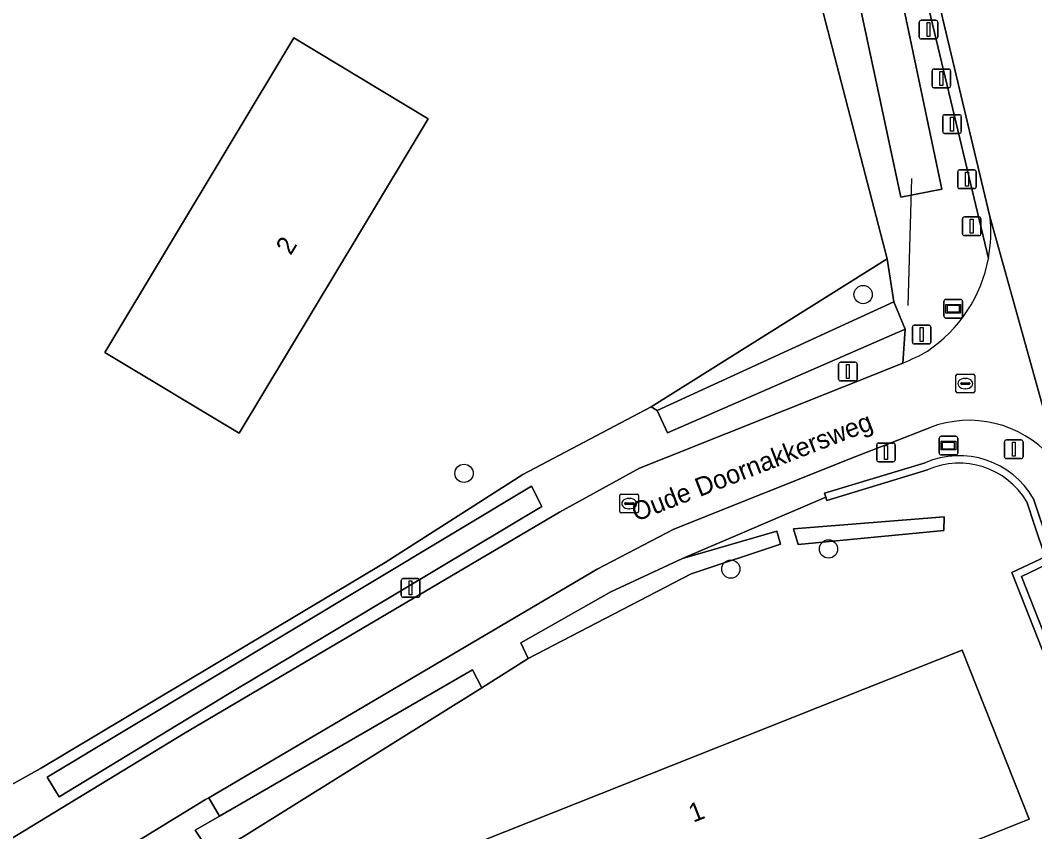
# Model space of a CAD drawing. Extents: x 164494 to 166241, y 382475 to 384495.
# Drawn here: x 164761.6 to 164815.9, y 383480 to 383523.4 of the extents above; entities that cross this region are included whole.
import ezdxf

# ---------------------------------------------------------------- set-up
doc = ezdxf.new("R2010")
doc.units = 0
for name, color, linetype in [('IMGEO_Afsluitpaal', 7, 'Continuous'), ('IMGEO_Berm_halfverhard', 7, 'Continuous'), ('IMGEO_Boom', 7, 'Continuous'), ('IMGEO_Duiker', 7, 'Continuous'), ('IMGEO_Erf', 7, 'Continuous'), ('IMGEO_Groenvoorziening', 7, 'Continuous'), ('IMGEO_Haag', 7, 'Continuous'), ('IMGEO_Lichtmast', 7, 'Continuous'), ('IMGEO_Openbare_ruimte_label', 7, 'Continuous'), ('IMGEO_Pand', 7, 'Continuous'), ('IMGEO_Pand_nummerreeks', 7, 'Continuous'), ('IMGEO_Rijbaan_lokaal_gesloten', 7, 'Continuous'), ('IMGEO_Rijbaan_lokaal_open', 7, 'Continuous'), ('IMGEO_Rioolput', 7, 'Continuous'), ('IMGEO_Straatnaambord', 7, 'Continuous'), ('IMGEO_Verklikker', 7, 'Continuous'), ('IMGEO_Voetpad_open', 7, 'Continuous'), ('IMGEO_Waterloop', 7, 'Continuous')]:
    doc.layers.add(name, color=color, linetype=linetype)

msp = doc.modelspace()

# ---------------------------------------------------------------- linework, layer by layer
at = {"layer": 'IMGEO_Afsluitpaal'}
for p, q in [((164809.71, 383522.472), (164809.71, 383523.272)), ((164809.71, 383523.272), (164809.71, 383522.472)), ((164809.81, 383523.372), (164810.6, 383523.372)), ((164810.6, 383523.372), (164809.81, 383523.372)), ((164810.7, 383523.272), (164810.7, 383522.472)), ((164810.7, 383522.472), (164810.7, 383523.272)), ((164810.6, 383522.372), (164809.81, 383522.372)), ((164809.81, 383522.372), (164810.6, 383522.372)), ((164810.396, 383519.864), (164810.396, 383520.664)), ((164810.396, 383520.664), (164810.396, 383519.864)), ((164810.496, 383520.764), (164811.286, 383520.764)), ((164811.286, 383520.764), (164810.496, 383520.764)), ((164811.386, 383520.664), (164811.386, 383519.864)), ((164811.386, 383519.864), (164811.386, 383520.664)), ((164811.286, 383519.764), (164810.496, 383519.764)), ((164810.496, 383519.764), (164811.286, 383519.764)), ((164810.968, 383517.418), (164810.968, 383518.218)), ((164810.968, 383518.218), (164810.968, 383517.418)), ((164811.068, 383518.318), (164811.858, 383518.318)), ((164811.858, 383518.318), (164811.068, 383518.318)), ((164811.958, 383518.218), (164811.958, 383517.418)), ((164811.958, 383517.418), (164811.958, 383518.218)), ((164811.858, 383517.318), (164811.068, 383517.318)), ((164811.068, 383517.318), (164811.858, 383517.318)), ((164811.766, 383514.464), (164811.766, 383515.264)), ((164811.766, 383515.264), (164811.766, 383514.464)), ((164811.866, 383515.364), (164812.656, 383515.364)), ((164812.656, 383515.364), (164811.866, 383515.364)), ((164812.756, 383515.264), (164812.756, 383514.464)), ((164812.756, 383514.464), (164812.756, 383515.264)), ((164812.656, 383514.364), (164811.866, 383514.364)), ((164811.866, 383514.364), (164812.656, 383514.364)), ((164812.021, 383511.95), (164812.021, 383512.75)), ((164812.021, 383512.75), (164812.021, 383511.95)), ((164812.121, 383512.85), (164812.911, 383512.85)), ((164812.911, 383512.85), (164812.121, 383512.85)), ((164813.011, 383512.75), (164813.011, 383511.95)), ((164813.011, 383511.95), (164813.011, 383512.75)), ((164812.911, 383511.85), (164812.121, 383511.85)), ((164812.121, 383511.85), (164812.911, 383511.85)), ((164809.341, 383506.155), (164809.341, 383506.955)), ((164809.341, 383506.955), (164809.341, 383506.155)), ((164809.441, 383507.055), (164810.231, 383507.055)), ((164810.231, 383507.055), (164809.441, 383507.055)), ((164810.331, 383506.955), (164810.331, 383506.155)), ((164810.331, 383506.155), (164810.331, 383506.955)), ((164810.231, 383506.055), (164809.441, 383506.055)), ((164809.441, 383506.055), (164810.231, 383506.055)), ((164814.269, 383500.022), (164814.269, 383500.822)), ((164814.269, 383500.822), (164814.269, 383500.022)), ((164814.369, 383500.922), (164815.159, 383500.922)), ((164815.159, 383500.922), (164814.369, 383500.922)), ((164815.259, 383500.822), (164815.259, 383500.022)), ((164815.259, 383500.022), (164815.259, 383500.822)), ((164807.433, 383499.852), (164807.433, 383500.652)), ((164807.433, 383500.652), (164807.433, 383499.852)), ((164807.533, 383500.752), (164808.323, 383500.752)), ((164808.323, 383500.752), (164807.533, 383500.752)), ((164808.423, 383500.652), (164808.423, 383499.852)), ((164808.423, 383499.852), (164808.423, 383500.652)), ((164808.323, 383499.752), (164807.533, 383499.752)), ((164807.533, 383499.752), (164808.323, 383499.752)), ((164815.159, 383499.922), (164814.369, 383499.922)), ((164814.369, 383499.922), (164815.159, 383499.922))]:
    msp.add_line(p, q, dxfattribs=at)
for points in [[(164810.13, 383523.247), (164810.28, 383523.247), (164810.28, 383522.497), (164810.13, 383522.497), (164810.13, 383523.247)], [(164810.816, 383520.639), (164810.966, 383520.639), (164810.966, 383519.889), (164810.816, 383519.889), (164810.816, 383520.639)], [(164811.388, 383518.193), (164811.538, 383518.193), (164811.538, 383517.443), (164811.388, 383517.443), (164811.388, 383518.193)], [(164812.186, 383515.239), (164812.336, 383515.239), (164812.336, 383514.489), (164812.186, 383514.489), (164812.186, 383515.239)], [(164812.441, 383512.725), (164812.591, 383512.725), (164812.591, 383511.975), (164812.441, 383511.975), (164812.441, 383512.725)], [(164809.761, 383506.93), (164809.911, 383506.93), (164809.911, 383506.18), (164809.761, 383506.18), (164809.761, 383506.93)], [(164814.689, 383500.797), (164814.839, 383500.797), (164814.839, 383500.047), (164814.689, 383500.047), (164814.689, 383500.797)], [(164807.853, 383500.627), (164808.003, 383500.627), (164808.003, 383499.877), (164807.853, 383499.877), (164807.853, 383500.627)]]:
    msp.add_lwpolyline(points, dxfattribs=at)
for centre, start, end in [((164809.81, 383523.272), 90, 180), ((164809.81, 383523.272), 90, 180), ((164810.6, 383523.272), 0, 90), ((164810.6, 383523.272), 360, 90), ((164809.81, 383522.472), 180, 270), ((164809.81, 383522.472), 180, 270), ((164810.6, 383522.472), 270, 0), ((164810.6, 383522.472), 270, 0), ((164810.496, 383520.664), 90, 180), ((164810.496, 383520.664), 90, 180), ((164811.286, 383520.664), 0, 90), ((164811.286, 383520.664), 360, 90), ((164810.496, 383519.864), 180, 270), ((164810.496, 383519.864), 180, 270), ((164811.286, 383519.864), 270, 0), ((164811.286, 383519.864), 270, 0), ((164811.068, 383518.218), 90, 180), ((164811.068, 383518.218), 90, 180), ((164811.858, 383518.218), 0, 90), ((164811.858, 383518.218), 360, 90), ((164811.068, 383517.418), 180, 270), ((164811.068, 383517.418), 180, 270), ((164811.858, 383517.418), 270, 0), ((164811.858, 383517.418), 270, 0), ((164811.866, 383515.264), 90, 180), ((164811.866, 383515.264), 90, 180), ((164812.656, 383515.264), 0, 90), ((164812.656, 383515.264), 360, 90), ((164811.866, 383514.464), 180, 270), ((164811.866, 383514.464), 180, 270), ((164812.656, 383514.464), 270, 0), ((164812.656, 383514.464), 270, 0), ((164812.121, 383512.75), 90, 180), ((164812.121, 383512.75), 90, 180), ((164812.911, 383512.75), 0, 90), ((164812.911, 383512.75), 360, 90), ((164812.121, 383511.95), 180, 270), ((164812.121, 383511.95), 180, 270), ((164812.911, 383511.95), 270, 0), ((164812.911, 383511.95), 270, 0), ((164809.441, 383506.955), 90, 180), ((164809.441, 383506.955), 90, 180), ((164810.231, 383506.955), 0, 90), ((164810.231, 383506.955), 360, 90), ((164809.441, 383506.155), 180, 270), ((164809.441, 383506.155), 180, 270), ((164810.231, 383506.155), 270, 0), ((164810.231, 383506.155), 270, 0), ((164814.369, 383500.822), 90, 180), ((164814.369, 383500.822), 90, 180), ((164815.159, 383500.822), 0, 90), ((164815.159, 383500.822), 360, 90), ((164807.533, 383500.652), 90, 180), ((164807.533, 383500.652), 90, 180), ((164808.323, 383500.652), 0, 90), ((164808.323, 383500.652), 360, 90), ((164807.533, 383499.852), 180, 270), ((164807.533, 383499.852), 180, 270), ((164808.323, 383499.852), 270, 0), ((164808.323, 383499.852), 270, 0), ((164814.369, 383500.022), 180, 270), ((164814.369, 383500.022), 180, 270), ((164815.159, 383500.022), 270, 0), ((164815.159, 383500.022), 270, 0)]:
    msp.add_arc(centre, 0.1, start, end, dxfattribs=at)
at = {"layer": 'IMGEO_Berm_halfverhard'}
for points in [[(164809.061, 383531.452), (164808.405, 383531.618), (164813.411, 383510.632)], [(164813.492, 383512.877), (164809.061, 383531.452)]]:
    msp.add_lwpolyline(points, dxfattribs=at)
msp.add_arc((164805.747, 383512.032), 7.791, 349.6448, 6.2225, dxfattribs=at)
at = {"layer": 'IMGEO_Boom'}
for centre in [(164806.708, 383508.699), (164785.363, 383499.133), (164804.856, 383495.089), (164799.632, 383494.011)]:
    msp.add_circle(centre, 0.489, dxfattribs=at)
at = {"layer": 'IMGEO_Duiker'}
msp.add_lwpolyline([(164809.12, 383508.11), (164809.318, 383514.904)], dxfattribs=at)
at = {"layer": 'IMGEO_Erf'}
for points in [[(164662.344, 383448.801), (164663.225, 383448.827), (164664.07, 383448.843), (164665.63, 383449.11), (164723.453, 383461.907), (164744.242, 383472.417), (164757.54, 383480.473), (164762.712, 383483.342), (164781.141, 383494.371), (164788.505, 383499.077), (164795.364, 383502.697), (164807.992, 383510.616), (164802.122, 383533.207)], [(164810.159, 383499.318), (164804.764, 383497.685), (164804.71, 383497.863), (164797.054, 383494.584), (164802.084, 383496.046), (164802.293, 383495.345), (164797.502, 383493.764), (164788.789, 383489.23), (164786.318, 383487.654), (164773.89, 383479.902), (164773.61, 383479.727), (164771.873, 383478.714), (164781.789, 383463.825), (164783.794, 383461.004), (164785.335, 383462.011), (164820.036, 383413.911)], [(164820.222, 383475.231), (164818.103, 383474.421), (164822.948, 383462.439), (164818.313, 383460.564), (164815.183, 383459.298), (164810.468, 383457.391), (164808.413, 383462.473), (164813.128, 383464.38), (164810.263, 383471.466), (164813.393, 383472.732), (164818.028, 383474.606), (164817.957, 383474.793), (164820.044, 383475.591), (164817.327, 383479.981), (164817.068, 383480.286), (164819.267, 383482.152), (164814.665, 383493.821), (164816.44, 383494.67), (164815.874, 383496.362), (164815.456, 383497.612)]]:
    msp.add_lwpolyline(points, dxfattribs=at)
for points in [[(164776.262, 383522.425), (164783.449, 383518.106), (164779.823, 383512.072), (164773.337, 383501.281), (164766.151, 383505.6)], [(164803.242, 383495.324), (164802.984, 383496.166), (164811.041, 383496.811), (164811.02, 383496.072)], [(164810.948, 383478.786), (164803.466, 383475.813), (164803.938, 383474.624), (164801.265, 383473.562), (164800.793, 383474.75), (164784.725, 383468.365), (164782.975, 383472.768), (164781.129, 383477.414), (164811.998, 383489.681), (164815.594, 383480.632)]]:
    msp.add_lwpolyline(points, close=True, dxfattribs=at)
msp.add_arc((164811.852, 383495.497), 4.179, 30.4025, 113.8932, dxfattribs=at)
at = {"layer": 'IMGEO_Groenvoorziening'}
for points in [[(164808.405, 383531.618), (164802.122, 383533.207), (164807.992, 383510.616), (164808.342, 383508.303), (164808.959, 383506.852), (164808.828, 383505.036)], [(164813.411, 383510.632), (164808.405, 383531.618)], [(164790.471, 383497.065), (164794.753, 383499.407), (164796.221, 383500), (164808.828, 383505.036), (164808.959, 383506.852), (164796.236, 383501.305), (164795.697, 383502.499), (164795.364, 383502.697), (164788.505, 383499.077), (164781.141, 383494.371), (164762.712, 383483.342), (164757.54, 383480.473), (164757.747, 383479.263), (164744.81, 383471.136), (164730.536, 383464.501), (164723.693, 383461.162), (164723.453, 383461.907), (164665.63, 383449.11), (164664.07, 383448.843), (164663.225, 383448.827), (164662.344, 383448.801)], [(164810.262, 383501.572), (164806.227, 383500), (164796.587, 383496.145), (164792.485, 383494.012), (164771.708, 383481.781), (164772.275, 383480.798), (164785.82, 383488.625), (164786.318, 383487.654), (164788.789, 383489.23), (164788.407, 383490.058), (164793.213, 383492.801), (164797.054, 383494.584), (164804.71, 383497.863), (164804.648, 383498.068), (164810.02, 383499.694)], [(164810.02, 383499.694), (164804.648, 383498.068), (164804.71, 383497.863), (164804.764, 383497.685), (164810.159, 383499.318)], [(164815.456, 383497.612), (164815.874, 383496.362), (164816.44, 383494.67), (164814.665, 383493.821), (164819.267, 383482.152), (164817.068, 383480.286), (164817.327, 383479.981), (164819.744, 383482.032), (164815.174, 383493.621), (164816.931, 383494.462), (164816.253, 383496.489), (164815.822, 383497.777)], [(164815.822, 383497.777), (164816.253, 383496.489)], [(164736.073, 383464.54), (164745.588, 383470.135), (164770.361, 383485.201), (164790.471, 383497.065)], [(164816.931, 383494.462), (164815.174, 383493.621), (164819.744, 383482.032)]]:
    msp.add_lwpolyline(points, dxfattribs=at)
for points in [[(164808.733, 383513.907), (164805.515, 383528.951), (164806.626, 383529.158), (164807.754, 383529.369), (164810.916, 383514.331)], [(164795.697, 383502.499), (164808.342, 383508.303), (164807.992, 383510.616), (164795.364, 383502.697)], [(164763.702, 383481.825), (164763.059, 383482.881), (164788.979, 383498.441), (164789.529, 383497.361), (164772.799, 383487.358)]]:
    msp.add_lwpolyline(points, close=True, dxfattribs=at)
for centre, radius, start, end in [((164805.888, 383512.03), 7.652, 303.7934, 349.4738), ((164805.021, 383514.606), 10.299, 291.6906, 299.8261), ((164812.384, 383496.117), 5.853, 41.6255, 111.2543), ((164811.851, 383495.498), 4.578, 29.8517, 113.5808), ((164811.851, 383495.498), 4.578, 29.8517, 113.5808), ((164811.852, 383495.497), 4.179, 30.4025, 113.8932)]:
    msp.add_arc(centre, radius, start, end, dxfattribs=at)
at = {"layer": 'IMGEO_Haag'}
for points in [[(164810.02, 383499.694), (164804.648, 383498.068), (164804.71, 383497.863), (164804.764, 383497.685), (164810.159, 383499.318)], [(164815.456, 383497.612), (164815.874, 383496.362), (164816.44, 383494.67), (164814.665, 383493.821), (164819.267, 383482.152), (164817.068, 383480.286), (164817.327, 383479.981), (164819.744, 383482.032), (164815.174, 383493.621), (164816.931, 383494.462), (164816.253, 383496.489), (164815.822, 383497.777)]]:
    msp.add_lwpolyline(points, dxfattribs=at)
for centre, radius, start, end in [((164811.851, 383495.498), 4.578, 29.8517, 113.5808), ((164811.852, 383495.497), 4.179, 30.4025, 113.8932)]:
    msp.add_arc(centre, radius, start, end, dxfattribs=at)
at = {"layer": 'IMGEO_Lichtmast'}
for p, q in [((164805.399, 383504.18), (164805.399, 383504.98)), ((164805.399, 383504.98), (164805.399, 383504.18)), ((164805.499, 383505.08), (164806.289, 383505.08)), ((164806.289, 383505.08), (164805.499, 383505.08)), ((164806.389, 383504.98), (164806.389, 383504.18)), ((164806.389, 383504.18), (164806.389, 383504.98)), ((164806.289, 383504.08), (164805.499, 383504.08)), ((164805.499, 383504.08), (164806.289, 383504.08)), ((164782.008, 383492.602), (164782.008, 383493.402)), ((164782.008, 383493.402), (164782.008, 383492.602)), ((164782.108, 383493.502), (164782.898, 383493.502)), ((164782.898, 383493.502), (164782.108, 383493.502)), ((164782.998, 383493.402), (164782.998, 383492.602)), ((164782.998, 383492.602), (164782.998, 383493.402)), ((164782.898, 383492.502), (164782.108, 383492.502)), ((164782.108, 383492.502), (164782.898, 383492.502))]:
    msp.add_line(p, q, dxfattribs=at)
for points in [[(164805.819, 383504.955), (164805.969, 383504.955), (164805.969, 383504.205), (164805.819, 383504.205), (164805.819, 383504.955)], [(164782.428, 383493.377), (164782.578, 383493.377), (164782.578, 383492.627), (164782.428, 383492.627), (164782.428, 383493.377)]]:
    msp.add_lwpolyline(points, dxfattribs=at)
for centre, start, end in [((164805.499, 383504.98), 90, 180), ((164805.499, 383504.98), 90, 180), ((164806.289, 383504.98), 0, 90), ((164806.289, 383504.98), 360, 90), ((164805.499, 383504.18), 180, 270), ((164805.499, 383504.18), 180, 270), ((164806.289, 383504.18), 270, 0), ((164806.289, 383504.18), 270, 0), ((164782.108, 383493.402), 90, 180), ((164782.108, 383493.402), 90, 180), ((164782.898, 383493.402), 0, 90), ((164782.898, 383493.402), 360, 90), ((164782.108, 383492.602), 180, 270), ((164782.108, 383492.602), 180, 270), ((164782.898, 383492.602), 270, 0), ((164782.898, 383492.602), 270, 0)]:
    msp.add_arc(centre, 0.1, start, end, dxfattribs=at)
at = {"layer": 'IMGEO_Pand'}
for points in [[(164779.823, 383512.072), (164783.449, 383518.106), (164776.262, 383522.425), (164766.151, 383505.6), (164773.337, 383501.281)], [(164810.948, 383478.786), (164815.594, 383480.632), (164811.998, 383489.681), (164781.129, 383477.414), (164782.975, 383472.768), (164784.725, 383468.365), (164800.793, 383474.75), (164801.265, 383473.562), (164803.938, 383474.624), (164803.466, 383475.813)]]:
    msp.add_lwpolyline(points, close=True, dxfattribs=at)
at = {"layer": 'IMGEO_Rijbaan_lokaal_gesloten'}
msp.add_lwpolyline([(164795.714, 383585.957), (164804.751, 383549.355), (164809.061, 383531.452), (164813.492, 383512.877), (164817.267, 383499.308), (164817.305, 383499.255), (164817.603, 383499.346), (164817.989, 383498.175), (164818.638, 383496.089), (164820.143, 383491.554)], dxfattribs=at)
at = {"layer": 'IMGEO_Rijbaan_lokaal_open'}
for points in [[(164816.759, 383500.005), (164817.267, 383499.308), (164813.492, 383512.877)], [(164808.828, 383505.036), (164796.221, 383500), (164794.753, 383499.407), (164790.471, 383497.065), (164770.361, 383485.201), (164745.588, 383470.135), (164736.073, 383464.54)], [(164737.479, 383461.248), (164741.488, 383463.681), (164747.101, 383466.722), (164771.534, 383481.679), (164771.708, 383481.781), (164792.485, 383494.012), (164796.587, 383496.145), (164806.227, 383500), (164810.262, 383501.572)]]:
    msp.add_lwpolyline(points, dxfattribs=at)
for centre, radius, start, end in [((164805.747, 383512.032), 7.791, 349.6448, 6.2225), ((164805.888, 383512.03), 7.652, 303.7934, 349.4738), ((164805.021, 383514.606), 10.299, 291.6906, 299.8261), ((164812.384, 383496.117), 5.853, 41.6255, 111.2543)]:
    msp.add_arc(centre, radius, start, end, dxfattribs=at)
at = {"layer": 'IMGEO_Rioolput'}
for p, q in [((164811.673, 383503.509), (164811.673, 383504.361)), ((164811.748, 383504.435), (164812.6, 383504.435)), ((164812.161, 383504.215), (164812.186, 383504.215)), ((164812.674, 383504.361), (164812.674, 383503.509)), ((164811.932, 383503.929), (164811.932, 383503.941)), ((164812.37, 383503.892), (164811.972, 383503.892)), ((164811.975, 383503.978), (164812.373, 383503.978)), ((164812.184, 383503.655), (164812.159, 383503.655)), ((164812.416, 383503.941), (164812.416, 383503.929)), ((164812.6, 383503.435), (164811.748, 383503.435)), ((164793.696, 383497.09), (164793.696, 383497.942)), ((164793.771, 383498.016), (164794.623, 383498.016)), ((164793.998, 383497.559), (164794.396, 383497.559)), ((164794.184, 383497.796), (164794.209, 383497.796)), ((164794.697, 383497.942), (164794.697, 383497.09)), ((164794.623, 383497.016), (164793.771, 383497.016)), ((164793.955, 383497.51), (164793.955, 383497.522)), ((164794.393, 383497.473), (164793.995, 383497.473)), ((164794.207, 383497.236), (164794.182, 383497.236)), ((164794.439, 383497.522), (164794.439, 383497.51))]:
    msp.add_line(p, q, dxfattribs=at)
for points in [[(164811.673, 383503.509), (164811.673, 383504.361)], [(164811.748, 383504.435), (164812.6, 383504.435)], [(164812.674, 383504.361), (164812.674, 383503.509)], [(164812.6, 383503.435), (164811.748, 383503.435)], [(164793.696, 383497.09), (164793.696, 383497.942)], [(164793.771, 383498.016), (164794.623, 383498.016)], [(164794.697, 383497.942), (164794.697, 383497.09)], [(164794.623, 383497.016), (164793.771, 383497.016)]]:
    msp.add_lwpolyline(points, dxfattribs=at)
for centre, radius, start, end in [((164811.75, 383504.359), 0.0765, 91.552, 178.448), ((164811.75, 383504.359), 0.0765, 91.552, 178.448), ((164812.598, 383504.359), 0.0765, 1.552, 88.448), ((164812.598, 383504.359), 0.0765, 1.552, 88.448), ((164811.75, 383503.511), 0.0765, 181.552, 268.448), ((164811.75, 383503.511), 0.0765, 181.552, 268.448), ((164811.972, 383503.938), 0.0403, 85.8775, 175.7526), ((164811.969, 383503.928), 0.0366, 178.938, 274.7102), ((164812.373, 383503.935), 0.043, 264.8664, 352.4533), ((164812.377, 383503.94), 0.0386, 1.7309, 96.639), ((164812.598, 383503.511), 0.0765, 271.552, 358.448), ((164812.598, 383503.511), 0.0765, 271.552, 358.448), ((164793.773, 383497.94), 0.0765, 91.552, 178.448), ((164793.773, 383497.94), 0.0765, 91.552, 178.448), ((164793.995, 383497.519), 0.0403, 85.8775, 175.7526), ((164794.4, 383497.521), 0.0386, 1.7309, 96.639), ((164794.621, 383497.94), 0.0765, 1.552, 88.448), ((164794.621, 383497.94), 0.0765, 1.552, 88.448), ((164793.773, 383497.092), 0.0765, 181.552, 268.448), ((164793.773, 383497.092), 0.0765, 181.552, 268.448), ((164793.992, 383497.509), 0.0366, 178.938, 274.7102), ((164794.396, 383497.516), 0.043, 264.8664, 352.4533), ((164794.621, 383497.092), 0.0765, 271.552, 358.448), ((164794.621, 383497.092), 0.0765, 271.552, 358.448)]:
    msp.add_arc(centre, radius, start, end, dxfattribs=at)
for centre, major_axis, ratio, start_param, end_param in [((164812.16, 383503.935), (-0.387, 0.002), 0.722429, 4.712389, 7.853982), ((164812.185, 383503.935), (-0.39, 0.002), 0.717154, 1.570796, 4.712389), ((164794.183, 383497.516), (-0.387, 0.002), 0.722429, 4.712389, 7.853982), ((164794.208, 383497.516), (-0.39, 0.002), 0.717154, 1.570796, 4.712389)]:
    msp.add_ellipse(centre, major_axis=major_axis, ratio=ratio, start_param=start_param, end_param=end_param, dxfattribs=at)
at = {"layer": 'IMGEO_Straatnaambord'}
for p, q in [((164811.132, 383508.439), (164811.922, 383508.439)), ((164811.922, 383508.439), (164811.132, 383508.439)), ((164811.032, 383507.539), (164811.032, 383508.339)), ((164811.032, 383508.339), (164811.032, 383507.539)), ((164812.022, 383508.339), (164812.022, 383507.539)), ((164812.022, 383507.539), (164812.022, 383508.339)), ((164811.922, 383507.439), (164811.132, 383507.439)), ((164811.132, 383507.439), (164811.922, 383507.439))]:
    msp.add_line(p, q, dxfattribs=at)
for points in [[(164811.133, 383508.171), (164811.921, 383508.171), (164811.921, 383507.707), (164811.133, 383507.707), (164811.133, 383508.171)], [(164811.198, 383508.106), (164811.198, 383507.772), (164811.856, 383507.772), (164811.856, 383508.106), (164811.198, 383508.106)]]:
    msp.add_lwpolyline(points, dxfattribs=at)
for centre, start, end in [((164811.132, 383508.339), 90, 180), ((164811.132, 383508.339), 90, 180), ((164811.922, 383508.339), 0, 90), ((164811.922, 383508.339), 360, 90), ((164811.132, 383507.539), 180, 270), ((164811.132, 383507.539), 180, 270), ((164811.922, 383507.539), 270, 0), ((164811.922, 383507.539), 270, 0)]:
    msp.add_arc(centre, 0.1, start, end, dxfattribs=at)
at = {"layer": 'IMGEO_Verklikker'}
for p, q in [((164810.777, 383500.218), (164810.777, 383501.018)), ((164810.777, 383501.018), (164810.777, 383500.218)), ((164810.877, 383501.118), (164811.667, 383501.118)), ((164811.667, 383501.118), (164810.877, 383501.118)), ((164811.767, 383501.018), (164811.767, 383500.218)), ((164811.767, 383500.218), (164811.767, 383501.018)), ((164811.667, 383500.118), (164810.877, 383500.118)), ((164810.877, 383500.118), (164811.667, 383500.118))]:
    msp.add_line(p, q, dxfattribs=at)
for points in [[(164810.878, 383500.85), (164811.666, 383500.85), (164811.666, 383500.386), (164810.878, 383500.386), (164810.878, 383500.85)], [(164810.943, 383500.785), (164810.943, 383500.451), (164811.601, 383500.451), (164811.601, 383500.785), (164810.943, 383500.785)]]:
    msp.add_lwpolyline(points, dxfattribs=at)
for centre, start, end in [((164810.877, 383501.018), 90, 180), ((164810.877, 383501.018), 90, 180), ((164811.667, 383501.018), 0, 90), ((164811.667, 383501.018), 360, 90), ((164810.877, 383500.218), 180, 270), ((164810.877, 383500.218), 180, 270), ((164811.667, 383500.218), 270, 0), ((164811.667, 383500.218), 270, 0)]:
    msp.add_arc(centre, 0.1, start, end, dxfattribs=at)
at = {"layer": 'IMGEO_Voetpad_open'}
msp.add_lwpolyline([(164740.895, 383460.566), (164743.085, 383461.862), (164763.042, 383473.669), (164763.63, 383474.017), (164765.09, 383471.534), (164772.583, 383475.997), (164771.151, 383478.63), (164771.699, 383478.975), (164770.982, 383480.051), (164772.275, 383480.798), (164771.708, 383481.781), (164771.534, 383481.679), (164747.101, 383466.722), (164741.488, 383463.681), (164737.479, 383461.248)], dxfattribs=at)
at = {"layer": 'IMGEO_Waterloop'}
for points in [[(164808.733, 383513.907), (164810.916, 383514.331), (164807.754, 383529.369), (164806.626, 383529.158), (164805.515, 383528.951)], [(164808.342, 383508.303), (164795.697, 383502.499), (164796.236, 383501.305), (164808.959, 383506.852)], [(164788.979, 383498.441), (164763.059, 383482.881), (164763.702, 383481.825), (164772.799, 383487.358), (164789.529, 383497.361)], [(164803.242, 383495.324), (164811.02, 383496.072), (164811.041, 383496.811), (164802.984, 383496.166)], [(164788.789, 383489.23), (164797.502, 383493.764), (164802.293, 383495.345), (164802.084, 383496.046), (164797.054, 383494.584), (164793.213, 383492.801), (164788.407, 383490.058)], [(164786.318, 383487.654), (164785.82, 383488.625), (164772.275, 383480.798), (164770.982, 383480.051), (164771.699, 383478.975), (164771.873, 383478.714), (164773.61, 383479.727), (164773.89, 383479.902)]]:
    msp.add_lwpolyline(points, close=True, dxfattribs=at)

# ---------------------------------------------------------------- texts
at = {"layer": 'IMGEO_Openbare_ruimte_label'}
msp.add_text('Oude Doornakkersweg', height=1, rotation=21.2802, dxfattribs=at).set_placement((164794.563, 383496.542))
at = {"layer": 'IMGEO_Pand_nummerreeks'}
for s, rotation, p in [('2', 58.9937, (164776.09, 383510.753)), ('1', 21.675, (164797.625, 383480.439))]:
    msp.add_text(s, height=1, rotation=rotation, dxfattribs=at).set_placement(p)

doc.saveas('drawing.dxf')
